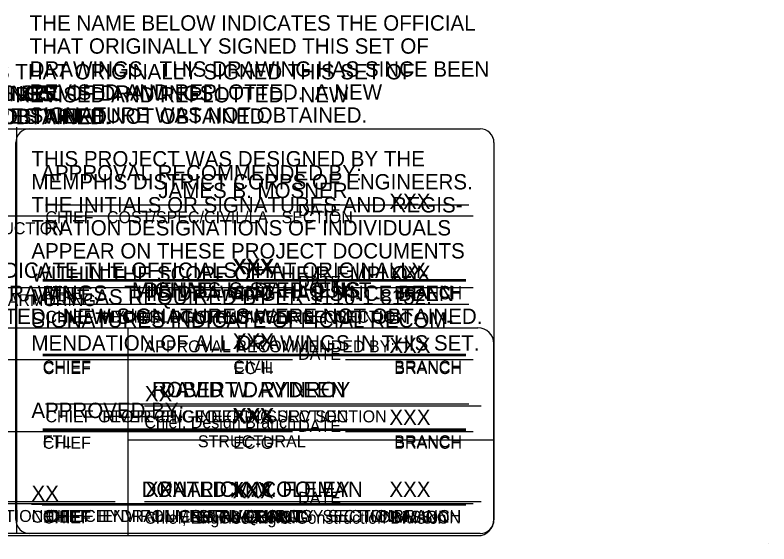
# Model space of a CAD drawing. Extents: x 0 to 2.77, y 0 to 1.73.
# Drawn here: x 2.2797 to 2.7708, y 0.0625 to 0.4071 of the extents above; entities that cross this region are included whole.
import ezdxf

# ---------------------------------------------------------------- set-up
doc = ezdxf.new("R2010")
doc.units = 0
for name, color, linetype in [('G-ANNO-TEXT', 7, 'Continuous'), ('G-ANNO-TEXT-HPOA', 7, 'Continuous'), ('G-ANNO-TEXT-HPOS', 7, 'Continuous'), ('G-ANNO-TEXT-MVKA', 7, 'Continuous'), ('G-ANNO-TEXT-MVKS', 7, 'Continuous'), ('G-ANNO-TEXT-MVMA', 7, 'Continuous'), ('G-ANNO-TEXT-MVMS', 7, 'Continuous'), ('G-ANNO-TEXT-MVNA', 7, 'Continuous'), ('G-ANNO-TEXT-MVNS', 7, 'Continuous'), ('G-ANNO-TEXT-MVPA', 7, 'Continuous'), ('G-ANNO-TEXT-MVPS', 7, 'Continuous'), ('G-ANNO-TEXT-MVRA', 7, 'Continuous'), ('G-ANNO-TEXT-MVRS', 7, 'Continuous'), ('G-ANNO-TEXT-MVSA', 7, 'Continuous'), ('G-ANNO-TEXT-MVSS', 7, 'Continuous')]:
    doc.layers.add(name, color=color, linetype=linetype)

msp = doc.modelspace()

# ---------------------------------------------------------------- linework, layer by layer
at = {"layer": 'G-ANNO-TEXT'}
msp.add_line((2.7708390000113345, 0.0625036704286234), (2.7708390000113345, 0.0625036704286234), dxfattribs=at)
at = {"layer": 'G-ANNO-TEXT-HPOS'}
for p, q in [((1.7683666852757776, 0.3329603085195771), (2.582691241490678, 0.33296251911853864)), ((1.7683666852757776, 0.3329603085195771), (2.582691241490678, 0.33296251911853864)), ((2.591691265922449, 0.3239625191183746), (2.5916912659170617, 0.0782958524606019)), ((2.591691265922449, 0.3239625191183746), (2.5916912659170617, 0.0782958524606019)), ((2.4603839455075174, 0.27613074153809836), (2.1740280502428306, 0.27613074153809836)), ((2.4603839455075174, 0.27613074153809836), (2.1740280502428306, 0.27613074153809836)), ((2.5781749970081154, 0.2761318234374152), (2.4950595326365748, 0.2761318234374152)), ((2.5781749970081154, 0.2761318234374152), (2.4950595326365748, 0.2761318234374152)), ((2.4603840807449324, 0.22925574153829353), (2.1740281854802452, 0.22925574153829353)), ((2.4603840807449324, 0.22925574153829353), (2.1740281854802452, 0.22925574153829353)), ((2.57817513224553, 0.22925682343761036), (2.4950596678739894, 0.22925682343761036)), ((2.57817513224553, 0.22925682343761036), (2.4950596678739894, 0.22925682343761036)), ((2.4603842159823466, 0.18238074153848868), (2.17402832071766, 0.18238074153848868)), ((2.4603842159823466, 0.18238074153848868), (2.17402832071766, 0.18238074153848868)), ((2.5781752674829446, 0.18238182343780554), (2.495059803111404, 0.18238182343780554)), ((2.5781752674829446, 0.18238182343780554), (2.495059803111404, 0.18238182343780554)), ((2.460384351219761, 0.13550574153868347), (2.1740284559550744, 0.13550574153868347)), ((2.460384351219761, 0.13550574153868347), (2.1740284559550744, 0.13550574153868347)), ((2.578175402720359, 0.13550682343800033), (2.495059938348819, 0.13550682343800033)), ((2.578175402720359, 0.13550682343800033), (2.495059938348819, 0.13550682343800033)), ((2.460384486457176, 0.08863074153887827), (2.174028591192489, 0.08863074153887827)), ((2.460384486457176, 0.08863074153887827), (2.174028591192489, 0.08863074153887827)), ((2.5781755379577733, 0.08863182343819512), (2.495060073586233, 0.08863182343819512)), ((2.5781755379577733, 0.08863182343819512), (2.495060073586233, 0.08863182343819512)), ((2.5826912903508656, 0.06929585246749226), (1.7683672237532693, 0.06929364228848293)), ((2.5826912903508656, 0.06929585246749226), (1.7683672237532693, 0.06929364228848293))]:
    msp.add_line(p, q, dxfattribs=at)
for centre, radius, start, end in [((2.5826912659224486, 0.32396251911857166), 0.008999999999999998, 359.99999999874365, 90.00015553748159), ((2.5826912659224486, 0.32396251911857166), 0.008999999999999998, 359.99999999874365, 90.00015553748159), ((2.582691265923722, 0.07829585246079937), 0.008999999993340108, 270.0001555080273, 359.99999999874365), ((2.582691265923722, 0.07829585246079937), 0.008999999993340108, 270.0001555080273, 359.99999999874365)]:
    msp.add_arc(centre, radius, start, end, dxfattribs=at)
at = {"layer": 'G-ANNO-TEXT-MVKS'}
for p, q in [((2.1253902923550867, 0.20331068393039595), (2.5812708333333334, 0.2033106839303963)), ((2.5832517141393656, 0.15222332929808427), (2.3640817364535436, 0.15222332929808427)), ((2.5916875, 0.13009650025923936), (2.35333056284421, 0.13009650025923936)), ((2.3448947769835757, 0.09001224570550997), (2.1257247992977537, 0.09001224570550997)), ((2.5832517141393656, 0.09001224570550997), (2.3640817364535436, 0.09001224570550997))]:
    msp.add_line(p, q, dxfattribs=at)
for points in [[(2.35333056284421, 0.06788541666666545), (2.35333056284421, 0.2033020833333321)], [(2.5916875, 0.07830208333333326), (2.5916875, 0.19288541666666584)], [(2.1249670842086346, 0.06789401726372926), (2.581270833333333, 0.06789401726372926)]]:
    msp.add_lwpolyline(points, dxfattribs=at)
for centre, start, end in [((2.5812708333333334, 0.19288541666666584), 360, 89.99999999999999), ((2.581270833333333, 0.07830208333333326), 270, 360)]:
    msp.add_arc(centre, 0.010416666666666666, start, end, dxfattribs=at)
at = {"layer": 'G-ANNO-TEXT-MVMS'}
for p, q in [((2.2891851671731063, 0.33297737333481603), (2.5826763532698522, 0.3329910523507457)), ((2.280181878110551, 0.2748269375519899), (2.280185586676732, 0.3239780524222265)), ((2.591676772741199, 0.3239910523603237), (2.5916767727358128, 0.07832438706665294)), ((2.2801860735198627, 0.07831055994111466), (2.280181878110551, 0.2748269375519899)), ((2.5731922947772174, 0.08816027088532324), (2.290348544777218, 0.08816027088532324)), ((2.582677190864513, 0.06932438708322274), (2.2891864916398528, 0.06931075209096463))]:
    msp.add_line(p, q, dxfattribs=at)
for centre, radius, start, end in [((2.2891855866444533, 0.3239773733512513), 0.008999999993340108, 90.00267043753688, 179.995676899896), ((2.5826767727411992, 0.32399105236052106), 0.008999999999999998, 359.99999999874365, 90.00267043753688), ((2.289186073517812, 0.07831075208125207), 0.008999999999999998, 180.00122320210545, 270.0026618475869), ((2.582676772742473, 0.07832438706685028), 0.008999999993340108, 270.0026618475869, 359.99999999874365)]:
    msp.add_arc(centre, radius, start, end, dxfattribs=at)
at = {"layer": 'G-ANNO-TEXT-MVNS'}
for p, q in [((1.6642008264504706, 0.3329735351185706), (2.582687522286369, 0.33296882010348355)), ((2.5916874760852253, 0.3239688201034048), (2.591687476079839, 0.07830215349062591)), ((2.5732967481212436, 0.2346375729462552), (2.2977863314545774, 0.2346375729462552)), ((2.5732967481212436, 0.1859709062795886), (2.2977863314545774, 0.1859709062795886)), ((2.5732967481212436, 0.137304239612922), (2.2977863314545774, 0.137304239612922)), ((2.5732967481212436, 0.08863757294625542), (2.297452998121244, 0.08863757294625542)), ((2.5826874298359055, 0.06930215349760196), (1.66420115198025, 0.06930687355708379))]:
    msp.add_line(p, q, dxfattribs=at)
for centre, radius, start, end in [((2.5826874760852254, 0.3239688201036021), 0.008999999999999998, 359.99999999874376, 89.9997058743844), ((2.582687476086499, 0.07830215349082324), 0.008999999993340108, 269.9997055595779, 359.99999999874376)]:
    msp.add_arc(centre, radius, start, end, dxfattribs=at)
at = {"layer": 'G-ANNO-TEXT-MVPS'}
for p, q in [((1.6656145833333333, 0.33296874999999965), (2.5826875, 0.33296874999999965)), ((2.5916875, 0.3239687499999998), (2.5916875, 0.07830208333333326)), ((2.5753020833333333, 0.2833020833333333), (2.299458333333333, 0.2833020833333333)), ((2.5752986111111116, 0.2184131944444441), (2.299454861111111, 0.2184131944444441)), ((2.5753055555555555, 0.1535243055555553), (2.299451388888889, 0.1535243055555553)), ((2.5753020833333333, 0.08863541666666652), (2.299447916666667, 0.08863541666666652)), ((2.5826875, 0.06930208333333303), (1.6656145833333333, 0.06930208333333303))]:
    msp.add_line(p, q, dxfattribs=at)
msp.add_lwpolyline([(2.280604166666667, 0.33396874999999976), (2.2806041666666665, 0.07030208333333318)], dxfattribs=at)
for centre, radius, start, end in [((2.5826823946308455, 0.3239666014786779), 0.008999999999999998, 4.973799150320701e-13, 90.00010277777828), ((2.582682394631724, 0.07829993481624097), 0.008999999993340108, 270.0001027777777, 360)]:
    msp.add_arc(centre, radius, start, end, dxfattribs=at)
at = {"layer": 'G-ANNO-TEXT-MVRS'}
for p, q in [((1.976679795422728, 0.3329770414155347), (2.582676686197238, 0.33299102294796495)), ((2.5916768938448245, 0.323991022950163), (2.5916768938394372, 0.07832435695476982)), ((2.5732810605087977, 0.23366510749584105), (2.297770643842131, 0.23366510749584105)), ((2.5732810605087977, 0.18499844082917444), (2.297770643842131, 0.18499844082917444)), ((2.5732810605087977, 0.13633177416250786), (2.297770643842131, 0.13633177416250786)), ((2.5732810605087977, 0.08766510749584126), (2.2974373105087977, 0.08766510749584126)), ((2.582677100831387, 0.06932435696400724), (1.9766806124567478, 0.0693104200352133))]:
    msp.add_line(p, q, dxfattribs=at)
for centre, radius, start, end in [((2.5826768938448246, 0.32399102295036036), 0.008999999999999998, 359.9999999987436, 90.00132192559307), ((2.5826768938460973, 0.07832435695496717), 0.008999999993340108, 270.00131770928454, 359.9999999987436)]:
    msp.add_arc(centre, radius, start, end, dxfattribs=at)
at = {"layer": 'G-ANNO-TEXT-MVSS'}
for p, q in [((1.3545333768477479, 0.3329608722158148), (2.5826912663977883, 0.33296250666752)), ((2.591691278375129, 0.32396250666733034), (2.591691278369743, 0.07829584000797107)), ((2.575307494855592, 0.21840909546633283), (2.299463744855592, 0.21840909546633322)), ((2.575314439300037, 0.15352020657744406), (2.29946027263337, 0.15352020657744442)), ((2.5753109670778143, 0.08863131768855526), (2.2994568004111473, 0.08863131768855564)), ((2.582691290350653, 0.06929584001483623), (1.3545338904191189, 0.06929420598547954))]:
    msp.add_line(p, q, dxfattribs=at)
msp.add_lwpolyline([(2.2806130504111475, 0.33296210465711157), (2.2806130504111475, 0.06929543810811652)], dxfattribs=at)
for centre, radius, start, end in [((2.5826912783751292, 0.3239625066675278), 0.008999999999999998, 359.9999999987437, 90.00007625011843), ((2.582691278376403, 0.07829584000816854), 0.008999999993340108, 270.00007623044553, 359.9999999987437)]:
    msp.add_arc(centre, radius, start, end, dxfattribs=at)

# ---------------------------------------------------------------- texts
at = {"layer": 'G-ANNO-TEXT-HPOA'}
for s, p in [('THE NAMES BELOW INDICATE THE OFFICIALS THAT ORIGINALLY SIGNED THIS SET OF DRAWINGS.', (1.7683838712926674, 0.35123377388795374)), ('THIS DRAWING HAS SINCE BEEN REVISED AND REPLOTTED.  NEW SIGNATURES WERE NOT OBTAINED.', (1.7683838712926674, 0.3362337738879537)), ('XXX', (2.5235678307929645, 0.2806627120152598)), ('XXX', (2.5235679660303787, 0.23378771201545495)), ('XXX', (2.5235681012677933, 0.18691271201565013)), ('XXX', (2.5235682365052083, 0.14003771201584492)), ('XXX', (2.5235683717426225, 0.09316271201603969))]:
    msp.add_text(s, height=0.01, rotation=360, dxfattribs=at).set_placement(p)
at = {"layer": 'G-ANNO-TEXT-HPOS'}
for s, p in [('DATE', (2.4641229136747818, 0.2761318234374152)), ('DATE', (2.4641229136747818, 0.2761318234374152)), ('CHIEF, ENGINEERING AND CONSTRUCTION', (2.0891124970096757, 0.26429738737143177)), ('CHIEF, ENGINEERING AND CONSTRUCTION', (2.0891124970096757, 0.26429738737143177)), ('DATE', (2.4641230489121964, 0.22925682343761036)), ('DATE', (2.4641230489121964, 0.22925682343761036)), ('CHIEF, LEVEES, FLOODWALLS, AND ARMORING', (2.0891126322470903, 0.21742238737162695)), ('CHIEF, LEVEES, FLOODWALLS, AND ARMORING', (2.0891126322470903, 0.21742238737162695)), ('DATE', (2.464123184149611, 0.18238182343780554)), ('DATE', (2.464123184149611, 0.18238182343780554)), ('DATE', (2.464123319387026, 0.13550682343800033)), ('DATE', (2.464123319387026, 0.13550682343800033)), ('DATE', (2.46412345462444, 0.08863182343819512)), ('DATE', (2.46412345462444, 0.08863182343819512)), ('COMMANDER, HURRICANE PROTECTION OFFICE', (2.089113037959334, 0.0767973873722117)), ('COMMANDER, HURRICANE PROTECTION OFFICE', (2.089113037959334, 0.0767973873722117))]:
    msp.add_text(s, height=0.0078125, rotation=360, dxfattribs=at).set_placement(p)
at = {"layer": 'G-ANNO-TEXT-MVKA'}
for s, p in [('THE NAMES BELOW INDICATE THE OFFICIALS THAT ORIGINALLY ', (2.124977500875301, 0.2358667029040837)), ('THE NAMES BELOW INDICATE THE OFFICIALS THAT ORIGINALLY ', (2.124977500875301, 0.2358667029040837)), ('SIGNED THIS SET OF DRAWINGS.  THIS DRAWING HAS SINCE BEEN ', (2.124977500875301, 0.2208667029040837)), ('SIGNED THIS SET OF DRAWINGS.  THIS DRAWING HAS SINCE BEEN ', (2.124977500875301, 0.2208667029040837)), ('REVISED AND REPLOTTED.  NEW SIGNATURES WERE NOT OBTAINED.', (2.124977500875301, 0.2058667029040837)), ('REVISED AND REPLOTTED.  NEW SIGNATURES WERE NOT OBTAINED.', (2.124977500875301, 0.2058667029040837)), ('XX', (2.3642624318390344, 0.15534703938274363)), ('XX', (2.3642624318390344, 0.15534703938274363)), ('XX', (2.3642624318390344, 0.09313595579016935)), ('XX', (2.3642624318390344, 0.09313595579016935))]:
    msp.add_text(s, height=0.01, rotation=360, dxfattribs=at).set_placement(p)
at = {"layer": 'G-ANNO-TEXT-MVKS'}
for s, p in [('APPROVAL RECOMMENDED BY:', (2.3639913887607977, 0.18735413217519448)), ('Chief, Design Branch', (2.3639913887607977, 0.1378489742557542)), ('Chief, Engineering & Construction Division', (2.3639913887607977, 0.0756378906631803))]:
    msp.add_text(s, height=0.0078125, rotation=359.99999999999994, dxfattribs=at).set_placement(p)
at = {"layer": 'G-ANNO-TEXT-MVMA'}
for s, p in [('THE NAME BELOW INDICATES THE OFFICIAL ', (2.289202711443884, 0.39693018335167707)), ('THAT ORIGINALLY SIGNED THIS SET OF ', (2.289202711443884, 0.38193018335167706)), ('DRAWINGS.  THIS DRAWING HAS SINCE BEEN ', (2.289202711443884, 0.36693018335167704)), ('REVISED AND REPLOTTED.  A NEW ', (2.289202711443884, 0.35193018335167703)), ('SIGNATURE WAS NOT OBTAINED.', (2.289202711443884, 0.33693018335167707))]:
    msp.add_text(s, height=0.01, dxfattribs=at).set_placement(p)
msp.add_text('XX', height=0.01, rotation=360, dxfattribs=at).set_placement((2.290369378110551, 0.09050404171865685))
at = {"layer": 'G-ANNO-TEXT-MVMS'}
for s, height, rotation, p in [('THIS PROJECT WAS DESIGNED BY THE ', 0.01, 360, (2.2903381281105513, 0.30847277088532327)), ('MEMPHIS DISTRICT CORPS OF ENGINEERS. ', 0.01, 360, (2.2903381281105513, 0.29347277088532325)), ('THE INITIALS OR SIGNATURES AND REGIS-', 0.01, 360, (2.2903381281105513, 0.27847277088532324)), ('TRATION DESIGNATIONS OF INDIVIDUALS ', 0.01, 360, (2.2903381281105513, 0.2634727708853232)), ('APPEAR ON THESE PROJECT DOCUMENTS ', 0.01, 360, (2.2903381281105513, 0.24847277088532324)), ('WITHIN THE SCOPE OF THEIR EMPLOY-', 0.01, 360, (2.2903381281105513, 0.23347277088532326)), ('MENT AS REQUIRED BY ER 1110-1-8152. ', 0.01, 360, (2.2903381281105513, 0.21847277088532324)), ('SIGNATURES INDICATE OFFICIAL RECOM-', 0.01, 360, (2.2903381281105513, 0.20347277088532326)), ('MENDATION OF ALL DRAWINGS IN THIS SET.', 0.01, 360, (2.2903381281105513, 0.18847277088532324)), ('APPROVED BY:', 0.01, 360, (2.2903277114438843, 0.14451443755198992)), ('CHIEF', 0.0078125, 360, (2.2903381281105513, 0.0763269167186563)), ('ENGR & CONST', 0.0078125, 359.99999999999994, (2.3868686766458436, 0.07631650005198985)), ('DIVISION', 0.0078125, 359.99999999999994, (2.516977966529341, 0.0763269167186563))]:
    msp.add_text(s, height=height, rotation=rotation, dxfattribs=at).set_placement(p)
at = {"layer": 'G-ANNO-TEXT-MVNA'}
for s, p in [('THE NAMES BELOW INDICATE THE OFFICIALS THAT ORIGINALLY SIGNED THIS SET OF DRAWINGS.', (1.6641953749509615, 0.35097588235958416)), ('THIS DRAWING HAS SINCE BEEN REVISED AND REPLOTTED.  NEW SIGNATURES WERE NOT OBTAINED.', (1.6641953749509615, 0.33597588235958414)), ('XXX', (2.4218867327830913, 0.23831669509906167)), ('XXX', (2.4214989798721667, 0.18965002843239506)), ('XXX', (2.421725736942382, 0.1409833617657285)), ('XXX', (2.4199179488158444, 0.09281885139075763))]:
    msp.add_text(s, height=0.01, rotation=360, dxfattribs=at).set_placement(p)
at = {"layer": 'G-ANNO-TEXT-MVNS'}
for s, p in [('FTL', (2.2977759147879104, 0.22280421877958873)), ('CIVIL', (2.4218907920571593, 0.2227938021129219)), ('BRANCH', (2.5267771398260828, 0.22280421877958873)), ('CHIEF', (2.2977759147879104, 0.17413755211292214)), ('CIVIL', (2.4218907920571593, 0.17412713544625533)), ('BRANCH', (2.5267771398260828, 0.17413755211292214)), ('FTL', (2.2977759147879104, 0.12547088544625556)), ('STRUCTURAL', (2.3988095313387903, 0.12546046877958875)), ('BRANCH', (2.5267771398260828, 0.12547088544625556)), ('CHIEF', (2.2977759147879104, 0.0768042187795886)), ('STRUCTURAL', (2.3991595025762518, 0.07679380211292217)), ('BRANCH', (2.526231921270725, 0.0768042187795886))]:
    msp.add_text(s, height=0.0078125, rotation=360, dxfattribs=at).set_placement(p)
at = {"layer": 'G-ANNO-TEXT-MVPA'}
for s, p in [('THE NAMES BELOW INDICATE THE OFFICIALS THAT ORIGINALLY SIGNED THIS SET OF DRAWINGS.', (1.6656250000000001, 0.35103565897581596)), ('THIS DRAWING HAS SINCE BEEN REVISED AND REPLOTTED.  NEW SIGNATURES WERE NOT OBTAINED.', (1.6656250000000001, 0.33603565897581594)), ('JAMES B. MOSNER', (2.372970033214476, 0.28783405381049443)), ('MICHAEL S. DAHLQUIST', (2.355889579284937, 0.2229451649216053)), ('DAVID W. RYDEEN', (2.3745217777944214, 0.1580562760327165)), ('PATRICK M. FOLEY', (2.3736112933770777, 0.0931673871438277))]:
    msp.add_text(s, height=0.01, rotation=360, dxfattribs=at).set_placement(p)
at = {"layer": 'G-ANNO-TEXT-MVPS'}
for s, p in [('CHIEF   COST/SPEC/CIVIL/LA   SECTION', (2.299458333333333, 0.2714687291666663)), ('CHIEF MECH/ELEC/STRU/ARCH   SECTION', (2.2994652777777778, 0.20659025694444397)), ('CHIEF GEOTECH/GEOLOGY/SURV SECTION', (2.2994618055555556, 0.14170136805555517)), ('CHIEF HYDRAULICS & HYDROLOGY SECTION', (2.299458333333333, 0.07681247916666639))]:
    msp.add_text(s, height=0.0078125, rotation=360, dxfattribs=at).set_placement(p)
at = {"layer": 'G-ANNO-TEXT-MVRA'}
for s, p in [('THE NAMES BELOW INDICATE THE OFFICIALS THAT ORIGINALLY SIGNED THIS SET OF ', (1.9766977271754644, 0.3651757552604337)), ('DRAWINGS.  THIS DRAWING HAS SINCE BEEN REVISED AND REPLOTTED.  NEW ', (1.9766977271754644, 0.3501757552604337)), ('XXX', (2.421181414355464, 0.23819707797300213)), ('XXX', (2.4215608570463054, 0.18953041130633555)), ('XXX', (2.4211731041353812, 0.14086374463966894)), ('XXX', (2.421399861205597, 0.09219707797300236))]:
    msp.add_text(s, height=0.01, rotation=360, dxfattribs=at).set_placement(p)
at = {"layer": 'G-ANNO-TEXT-MVRS'}
for s, height, rotation, p in [('APPROVAL RECOMMENDED BY:', 0.01, 360, (2.296760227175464, 0.2993109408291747)), ('CHIEF', 0.0078125, 360, (2.2977602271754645, 0.22183175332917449)), ('EC-D', 0.0078125, 359.99999999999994, (2.422181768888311, 0.22182133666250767)), ('BRANCH', 0.0078125, 359.99999999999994, (2.526761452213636, 0.22183175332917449)), ('CHIEF', 0.0078125, 360, (2.2977602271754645, 0.17316508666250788)), ('EC-H', 0.0078125, 359.99999999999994, (2.422181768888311, 0.17315466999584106)), ('BRANCH', 0.0078125, 359.99999999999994, (2.526761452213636, 0.17316508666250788)), ('CHIEF', 0.0078125, 360, (2.2977602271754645, 0.12449841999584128)), ('EC-G', 0.0078125, 359.99999999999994, (2.421844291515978, 0.12448800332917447)), ('BRANCH', 0.0078125, 359.99999999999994, (2.526761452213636, 0.12449841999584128)), ('CHIEF', 0.0078125, 360, (2.2977602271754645, 0.07583175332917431)), ('ENGINEERING', 0.0078125, 359.99999999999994, (2.3976253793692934, 0.07582133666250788)), ('DIVISION', 0.0078125, 359.99999999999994, (2.524400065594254, 0.07583175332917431))]:
    msp.add_text(s, height=height, rotation=rotation, dxfattribs=at).set_placement(p)
at = {"layer": 'G-ANNO-TEXT-MVSA'}
for s, p in [('DENNIS L. STEPHENS', (2.363394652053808, 0.2229410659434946)), ('ROBERT DAVINROY', (2.3688370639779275, 0.1580521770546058)), ('DONALD M. COLEMAN', (2.3621072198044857, 0.09316328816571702))]:
    msp.add_text(s, height=0.01, rotation=360, dxfattribs=at).set_placement(p)
at = {"layer": 'G-ANNO-TEXT-MVSS'}
for s, p in [('CHIEF  HYDROLOGIC ENGINEERING  SECTION', (2.2994741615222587, 0.2065861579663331)), ('CHIEF  RIVER  ENGINEERING SECTION', (2.2994706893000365, 0.1416972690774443)), ('CHIEF  ENVIRONMENTAL QUALITY  SECTION', (2.2994672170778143, 0.07680838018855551))]:
    msp.add_text(s, height=0.0078125, rotation=360, dxfattribs=at).set_placement(p)

doc.saveas('drawing.dxf')
